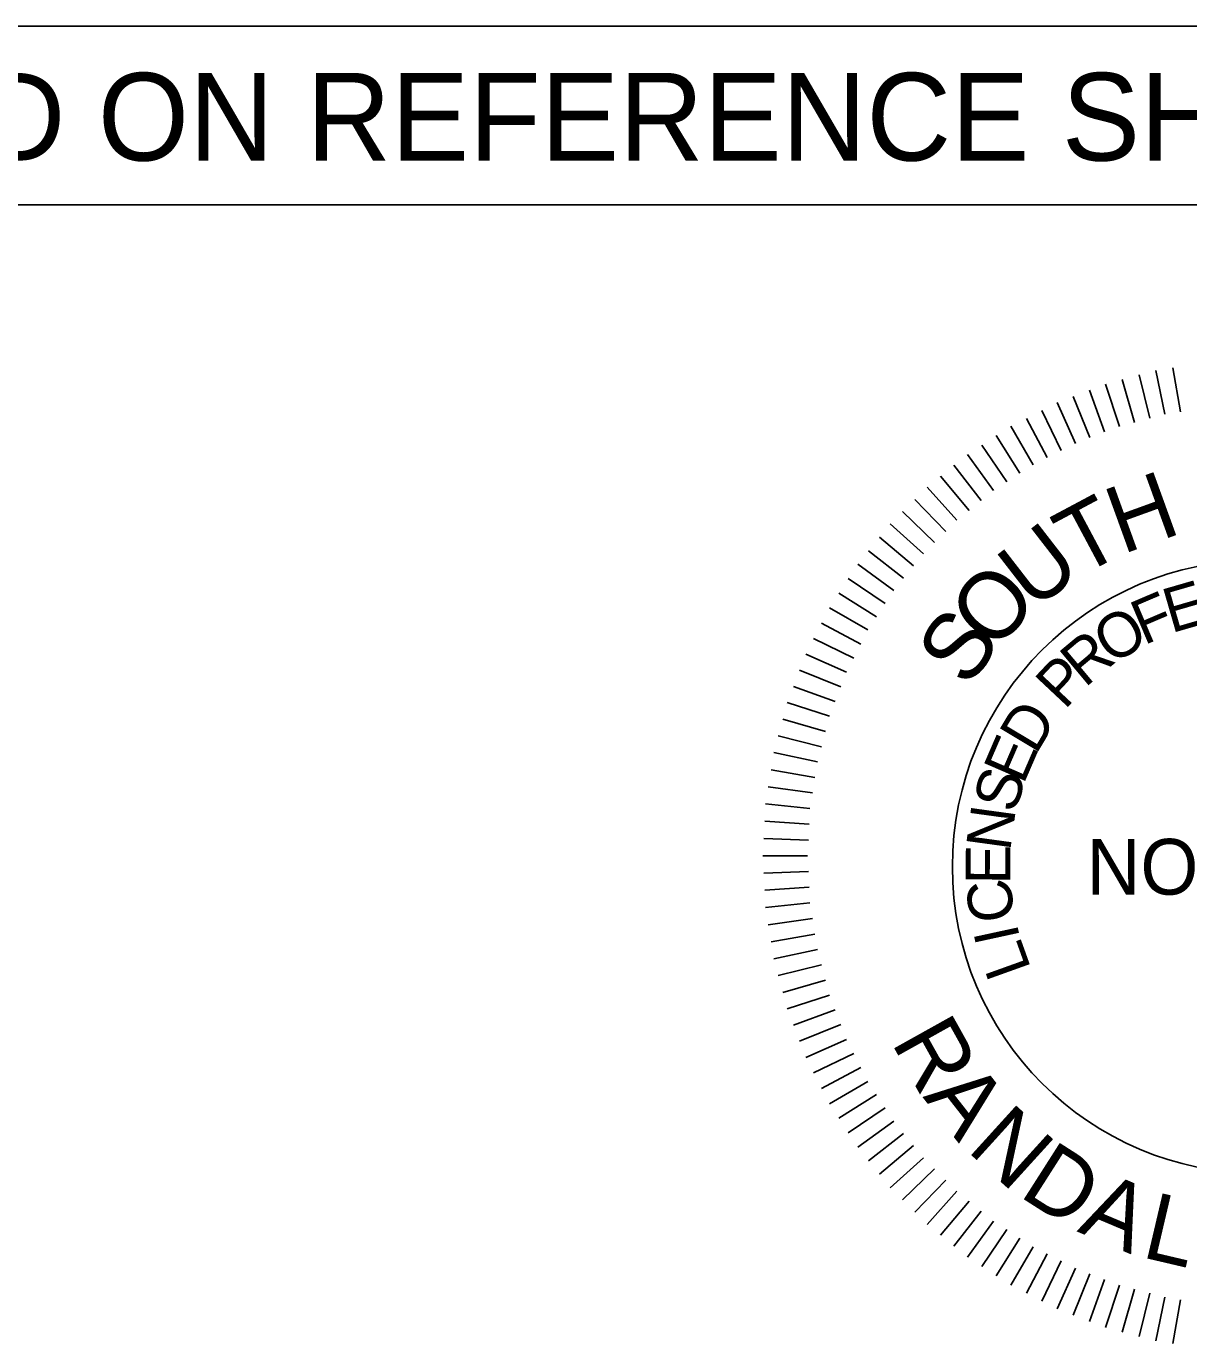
# Model space of a CAD drawing. Extents: x 1964377 to 1966966, y 1116414 to 1123213.
# Drawn here: x 1966773 to 1966865.8, y 1119136.7 to 1119241.9 of the extents above; entities that cross this region are included whole.
import ezdxf

# ---------------------------------------------------------------- set-up
doc = ezdxf.new("R2010")
doc.units = 0
doc.layers.add('RD_Sketch1', color=7, linetype='Continuous')
doc.layers.add('RD_TX_PEShield', color=7, linetype='Continuous')

msp = doc.modelspace()

# ---------------------------------------------------------------- linework, layer by layer
at = {"layer": 'RD_Sketch1'}
msp.add_lwpolyline([(1966596.19, 1119241.9), (1966896.61, 1119241.9), (1966896.61, 1119227.64), (1966596.19, 1119227.64)], close=True, dxfattribs=at)
at = {"layer": 'RD_TX_PEShield'}
for p, q in [((1966865.2, 1119211.13), (1966864.58, 1119214.63)), ((1966865.2, 1119211.13), (1966864.58, 1119214.63)), ((1966861.52, 1119210.28), (1966860.54, 1119213.7)), ((1966861.52, 1119210.28), (1966860.54, 1119213.7)), ((1966862.74, 1119210.61), (1966861.88, 1119214.06)), ((1966862.74, 1119210.61), (1966861.88, 1119214.06)), ((1966863.95, 1119210.93), (1966863.21, 1119214.41)), ((1966863.95, 1119210.93), (1966863.21, 1119214.41)), ((1966857.96, 1119209.06), (1966856.63, 1119212.35)), ((1966857.96, 1119209.06), (1966856.63, 1119212.35)), ((1966859.13, 1119209.51), (1966857.92, 1119212.85)), ((1966859.13, 1119209.51), (1966857.92, 1119212.85)), ((1966860.31, 1119209.96), (1966859.21, 1119213.34)), ((1966860.31, 1119209.96), (1966859.21, 1119213.34)), ((1966856.79, 1119208.6), (1966855.34, 1119211.86)), ((1966856.79, 1119208.6), (1966855.34, 1119211.86)), ((1966854.55, 1119207.46), (1966852.88, 1119210.6)), ((1966854.55, 1119207.46), (1966852.88, 1119210.6)), ((1966855.66, 1119208.03), (1966854.11, 1119211.23)), ((1966855.66, 1119208.03), (1966854.11, 1119211.23)), ((1966852.37, 1119206.21), (1966850.48, 1119209.22)), ((1966852.37, 1119206.21), (1966850.48, 1119209.22)), ((1966853.42, 1119206.89), (1966851.64, 1119209.97)), ((1966853.42, 1119206.89), (1966851.64, 1119209.97)), ((1966851.32, 1119205.52), (1966849.33, 1119208.47)), ((1966851.32, 1119205.52), (1966849.33, 1119208.47)), ((1966850.26, 1119204.84), (1966848.17, 1119207.72)), ((1966850.26, 1119204.84), (1966848.17, 1119207.72)), ((1966849.28, 1119204.04), (1966847.09, 1119206.85)), ((1966849.28, 1119204.04), (1966847.09, 1119206.85)), ((1966847.33, 1119202.46), (1966844.95, 1119205.11)), ((1966847.33, 1119202.46), (1966844.95, 1119205.11)), ((1966848.31, 1119203.25), (1966846.02, 1119205.98)), ((1966848.31, 1119203.25), (1966846.02, 1119205.98)), ((1966846.44, 1119201.57), (1966843.97, 1119204.13)), ((1966846.44, 1119201.57), (1966843.97, 1119204.13)), ((1966845.55, 1119200.68), (1966842.99, 1119203.15)), ((1966845.55, 1119200.68), (1966842.99, 1119203.15)), ((1966844.66, 1119199.79), (1966842.01, 1119202.18)), ((1966844.66, 1119199.79), (1966842.01, 1119202.18)), ((1966843.87, 1119198.82), (1966841.14, 1119201.1)), ((1966843.87, 1119198.82), (1966841.14, 1119201.1)), ((1966843.08, 1119197.84), (1966840.28, 1119200.03)), ((1966843.08, 1119197.84), (1966840.28, 1119200.03)), ((1966842.29, 1119196.86), (1966839.41, 1119198.95)), ((1966842.29, 1119196.86), (1966839.41, 1119198.95)), ((1966841.6, 1119195.81), (1966838.65, 1119197.8)), ((1966841.6, 1119195.81), (1966838.65, 1119197.8)), ((1966840.92, 1119194.75), (1966837.9, 1119196.64)), ((1966840.92, 1119194.75), (1966837.9, 1119196.64)), ((1966840.23, 1119193.7), (1966837.15, 1119195.48)), ((1966840.23, 1119193.7), (1966837.15, 1119195.48)), ((1966839.66, 1119192.58), (1966836.52, 1119194.25)), ((1966839.66, 1119192.58), (1966836.52, 1119194.25)), ((1966839.09, 1119191.46), (1966835.89, 1119193.02)), ((1966839.09, 1119191.46), (1966835.89, 1119193.02)), ((1966838.52, 1119190.34), (1966835.27, 1119191.78)), ((1966838.52, 1119190.34), (1966835.27, 1119191.78)), ((1966838.07, 1119189.16), (1966834.77, 1119190.49)), ((1966838.07, 1119189.16), (1966834.77, 1119190.49)), ((1966837.62, 1119187.99), (1966834.28, 1119189.2)), ((1966837.62, 1119187.99), (1966834.28, 1119189.2)), ((1966837.17, 1119186.81), (1966833.78, 1119187.91)), ((1966837.17, 1119186.81), (1966833.78, 1119187.91)), ((1966836.84, 1119185.6), (1966833.42, 1119186.58)), ((1966836.84, 1119185.6), (1966833.42, 1119186.58)), ((1966836.52, 1119184.38), (1966833.07, 1119185.25)), ((1966836.52, 1119184.38), (1966833.07, 1119185.25)), ((1966836.19, 1119183.17), (1966832.71, 1119183.91)), ((1966836.19, 1119183.17), (1966832.71, 1119183.91)), ((1966835.99, 1119181.93), (1966832.49, 1119182.54)), ((1966835.99, 1119181.93), (1966832.49, 1119182.54)), ((1966835.8, 1119180.69), (1966832.27, 1119181.18)), ((1966835.8, 1119180.69), (1966832.27, 1119181.18)), ((1966835.6, 1119179.44), (1966832.06, 1119179.82)), ((1966835.6, 1119179.44), (1966832.06, 1119179.82)), ((1966835.53, 1119178.19), (1966831.99, 1119178.43)), ((1966835.53, 1119178.19), (1966831.99, 1119178.43)), ((1966835.47, 1119176.93), (1966831.91, 1119177.06)), ((1966835.47, 1119176.93), (1966831.91, 1119177.06)), ((1966835.4, 1119175.68), (1966831.84, 1119175.68)), ((1966835.4, 1119175.68), (1966831.84, 1119175.68)), ((1966835.47, 1119174.42), (1966831.91, 1119174.29)), ((1966835.47, 1119174.42), (1966831.91, 1119174.29)), ((1966835.53, 1119173.16), (1966831.99, 1119172.92)), ((1966835.53, 1119173.16), (1966831.99, 1119172.92)), ((1966835.6, 1119171.91), (1966832.06, 1119171.54)), ((1966835.6, 1119171.91), (1966832.06, 1119171.54)), ((1966835.8, 1119170.67), (1966832.27, 1119170.17)), ((1966835.8, 1119170.67), (1966832.27, 1119170.17)), ((1966835.99, 1119169.42), (1966832.49, 1119168.81)), ((1966835.99, 1119169.42), (1966832.49, 1119168.81)), ((1966836.19, 1119168.18), (1966832.71, 1119167.44)), ((1966836.19, 1119168.18), (1966832.71, 1119167.44)), ((1966836.52, 1119166.97), (1966833.07, 1119166.11)), ((1966836.52, 1119166.97), (1966833.07, 1119166.11)), ((1966836.84, 1119165.75), (1966833.42, 1119164.77)), ((1966836.84, 1119165.75), (1966833.42, 1119164.77)), ((1966837.17, 1119164.54), (1966833.78, 1119163.44)), ((1966837.62, 1119163.36), (1966834.28, 1119162.15)), ((1966837.62, 1119163.36), (1966834.28, 1119162.15)), ((1966838.07, 1119162.19), (1966834.77, 1119160.86)), ((1966838.07, 1119162.19), (1966834.77, 1119160.86)), ((1966838.52, 1119161.01), (1966835.27, 1119159.57)), ((1966838.52, 1119161.01), (1966835.27, 1119159.57)), ((1966839.09, 1119159.89), (1966835.89, 1119158.33)), ((1966839.09, 1119159.89), (1966835.89, 1119158.33)), ((1966839.66, 1119158.77), (1966836.52, 1119157.1)), ((1966839.66, 1119158.77), (1966836.52, 1119157.1)), ((1966840.23, 1119157.65), (1966837.15, 1119155.87)), ((1966840.23, 1119157.65), (1966837.15, 1119155.87)), ((1966840.92, 1119156.6), (1966837.9, 1119154.71)), ((1966840.92, 1119156.6), (1966837.9, 1119154.71)), ((1966841.6, 1119155.54), (1966838.65, 1119153.56)), ((1966841.6, 1119155.54), (1966838.65, 1119153.56)), ((1966842.29, 1119154.49), (1966839.41, 1119152.4)), ((1966842.29, 1119154.49), (1966839.41, 1119152.4)), ((1966843.08, 1119153.51), (1966840.28, 1119151.32)), ((1966843.08, 1119153.51), (1966840.28, 1119151.32)), ((1966843.87, 1119152.53), (1966841.14, 1119150.25)), ((1966843.87, 1119152.53), (1966841.14, 1119150.25)), ((1966844.66, 1119151.56), (1966842.01, 1119149.17)), ((1966844.66, 1119151.56), (1966842.01, 1119149.17)), ((1966845.55, 1119150.67), (1966842.99, 1119148.2)), ((1966845.55, 1119150.67), (1966842.99, 1119148.2)), ((1966846.44, 1119149.78), (1966843.97, 1119147.22)), ((1966846.44, 1119149.78), (1966843.97, 1119147.22)), ((1966847.33, 1119148.89), (1966844.95, 1119146.24)), ((1966847.33, 1119148.89), (1966844.95, 1119146.24)), ((1966848.31, 1119148.1), (1966846.02, 1119145.37)), ((1966848.31, 1119148.1), (1966846.02, 1119145.37)), ((1966849.28, 1119147.31), (1966847.09, 1119144.5)), ((1966849.28, 1119147.31), (1966847.09, 1119144.5)), ((1966850.26, 1119146.51), (1966848.17, 1119143.63)), ((1966850.26, 1119146.51), (1966848.17, 1119143.63)), ((1966851.32, 1119145.83), (1966849.33, 1119142.88)), ((1966851.32, 1119145.83), (1966849.33, 1119142.88)), ((1966852.37, 1119145.14), (1966850.48, 1119142.13)), ((1966852.37, 1119145.14), (1966850.48, 1119142.13)), ((1966853.42, 1119144.46), (1966851.64, 1119141.38)), ((1966853.42, 1119144.46), (1966851.64, 1119141.38)), ((1966854.55, 1119143.89), (1966852.88, 1119140.75)), ((1966854.55, 1119143.89), (1966852.88, 1119140.75)), ((1966855.66, 1119143.32), (1966854.11, 1119140.12)), ((1966855.66, 1119143.32), (1966854.11, 1119140.12)), ((1966856.79, 1119142.75), (1966855.34, 1119139.49)), ((1966856.79, 1119142.75), (1966855.34, 1119139.49)), ((1966857.96, 1119142.3), (1966856.63, 1119139)), ((1966857.96, 1119142.3), (1966856.63, 1119139)), ((1966859.13, 1119141.85), (1966857.92, 1119138.5)), ((1966859.13, 1119141.85), (1966857.92, 1119138.5)), ((1966860.31, 1119141.39), (1966859.21, 1119138.01)), ((1966860.31, 1119141.39), (1966859.21, 1119138.01)), ((1966861.52, 1119141.07), (1966860.54, 1119137.65)), ((1966861.52, 1119141.07), (1966860.54, 1119137.65)), ((1966862.74, 1119140.74), (1966861.88, 1119137.29)), ((1966862.74, 1119140.74), (1966861.88, 1119137.29)), ((1966863.95, 1119140.42), (1966863.21, 1119136.94)), ((1966863.95, 1119140.42), (1966863.21, 1119136.94)), ((1966865.2, 1119140.22), (1966864.58, 1119136.72)), ((1966865.2, 1119140.22), (1966864.58, 1119136.72))]:
    msp.add_line(p, q, dxfattribs=at)
msp.add_circle((1966871.45, 1119174.8), 24.48, dxfattribs=at)

# ---------------------------------------------------------------- texts
at = {"layer": 'RD_Sketch1'}
msp.add_text('ALIGNMENT CONTROL CAN BE FOUND ON REFERENCE SHEET', height=7, dxfattribs=at).set_placement((1966599.83, 1119231.18))
at = {"layer": 'RD_TX_PEShield'}
for s, height, rotation, p in [('H', 5.34, 19.9102, (1966860.54, 1119199.72)), ('T', 5.34, 28.0947, (1966857.11, 1119197.91)), ('U', 5.34, 37.7726, (1966853.42, 1119195.17)), ('O', 5.34, 47.4504, (1966850.26, 1119191.85)), ('E', 3.56, 16.1843, (1966864.44, 1119193.43)), ('F', 3.56, 23.0853, (1966862.26, 1119192.46)), ('S', 5.34, 54.9027, (1966848.22, 1119188.96)), ('O', 3.56, 31.7869, (1966859.69, 1119190.86)), ('R', 3.56, 39.8902, (1966857.54, 1119189.04)), ('P', 3.56, 46.7912, (1966855.93, 1119187.27)), ('D', 3.56, 59.074, (1966853.63, 1119183.68)), ('E', 3.56, 66.5674, (1966852.63, 1119181.29)), ('S', 3.56, 73.4683, (1966851.98, 1119178.98)), ('N', 3.56, 82.17, (1966851.58, 1119175.98)), ('E', 3.56, 89.6633, (1966851.59, 1119173.38)), ('C', 3.56, 97.7667, (1966851.99, 1119170.6)), ('I', 3.56, 102.2511, (1966852.38, 1119169.09)), ('L', 3.56, 109.7445, (1966853.28, 1119166.65)), ('R', 5.34, 299.1493, (1966842.04, 1119160.82)), ('A', 5.34, 308.0877, (1966844.57, 1119156.42)), ('N', 5.34, 317.7655, (1966848.04, 1119152.17)), ('D', 5.34, 327.4433, (1966852.18, 1119148.56)), ('A', 5.34, 337.1212, (1966856.87, 1119145.69)), ('L', 5.34, 346.799, (1966861.97, 1119143.65))]:
    msp.add_text(s, height=height, rotation=rotation, dxfattribs=at).set_placement(p)
msp.add_text('NO. 24265', height=4.45, dxfattribs=at).set_placement((1966857.69, 1119172.57))

doc.saveas('drawing.dxf')
